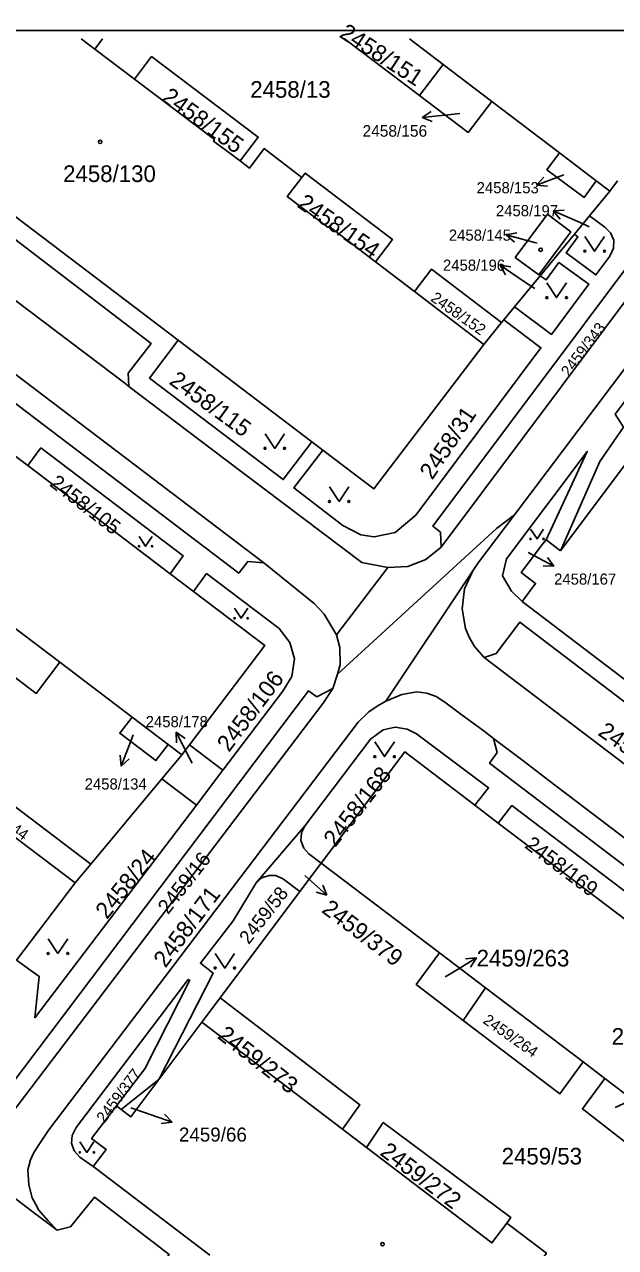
# Model space of a CAD drawing. Extents: x -606208 to -605570, y -1157873 to -1157573.
# Drawn here: x -605930.7 to -605870.3, y -1157700.9 to -1157575.9 of the extents above; entities that cross this region are included whole.
import ezdxf

# ---------------------------------------------------------------- set-up
doc = ezdxf.new("R2010")
doc.units = 0
doc.layers.add('Vrstva 1', color=7, linetype='Continuous')
doc.layers.add('Vrstva 62', color=7, linetype='Continuous')

msp = doc.modelspace()

# ---------------------------------------------------------------- linework, layer by layer
at = {"layer": 'Vrstva 1'}
msp.add_lwpolyline([(-606203.28, -1157873.46), (-605573.29, -1157873.46), (-605573.29, -1157576.47), (-606203.28, -1157576.47)], close=True, dxfattribs=at)
at = {"layer": 'Vrstva 62'}
for p, q in [((-605891.36, -1157577.34), (-605887.93, -1157579.95)), ((-605923.54, -1157578.38), (-605919.48, -1157581.46)), ((-605890.35, -1157583.14), (-605887.93, -1157579.95)), ((-605887.93, -1157579.95), (-605882.93, -1157583.75)), ((-605876.04, -1157588.98), (-605882.93, -1157583.75)), ((-605906.26, -1157630.89), (-605966.57, -1157585.11)), ((-605890.08, -1157585.38), (-605889.13, -1157584.78)), ((-605887.09, -1157585.07), (-605890.08, -1157585.38)), ((-605886.23, -1157584.98), (-605887.09, -1157585.07)), ((-605915.01, -1157608.14), (-605943.82, -1157586.26)), ((-605890.08, -1157585.38), (-605889.03, -1157585.78)), ((-605888.11, -1157629.29), (-605855.73, -1157585.95)), ((-605876.04, -1157588.98), (-605872.28, -1157591.84)), ((-605875.58, -1157591.22), (-605878.38, -1157592.29)), ((-605878.38, -1157592.29), (-605877.63, -1157591.47)), ((-605878.38, -1157592.29), (-605877.27, -1157592.4)), ((-605870.88, -1157592.9), (-605872.28, -1157591.84)), ((-605870.09, -1157591.86), (-605870.88, -1157592.9)), ((-605872.96, -1157595.43), (-605870.88, -1157592.9)), ((-605876.67, -1157594.9), (-605875.55, -1157594.85)), ((-605873.93, -1157596.12), (-605876.67, -1157594.9)), ((-605876.67, -1157594.9), (-605875.96, -1157595.76)), ((-605874.5, -1157597.3), (-605872.96, -1157595.43)), ((-605873, -1157596.54), (-605873.93, -1157596.12)), ((-605881.48, -1157597.38), (-605880.38, -1157597.16)), ((-605878.58, -1157598.16), (-605881.48, -1157597.38)), ((-605881.48, -1157597.38), (-605880.64, -1157598.13)), ((-605878, -1157601.55), (-605874.5, -1157597.3)), ((-605878.31, -1157598.23), (-605878.58, -1157598.16)), ((-605894.85, -1157600.12), (-605890.85, -1157603.17)), ((-605879.61, -1157602.16), (-605882.1, -1157600.48)), ((-605882.1, -1157600.48), (-605880.99, -1157600.63)), ((-605882.1, -1157600.48), (-605881.55, -1157601.46)), ((-605880.62, -1157604.74), (-605878, -1157601.55)), ((-605878.56, -1157602.87), (-605879.61, -1157602.16)), ((-605883.77, -1157608.56), (-605890.85, -1157603.17)), ((-605881.71, -1157606.06), (-605880.62, -1157604.74)), ((-605881.94, -1157606.34), (-605883.77, -1157608.56)), ((-605881.94, -1157606.34), (-605881.71, -1157606.06)), ((-605901.35, -1157618.51), (-605915.01, -1157608.14)), ((-605920.04, -1157612.86), (-605920.12, -1157611.51)), ((-605900.22, -1157619.37), (-605901.35, -1157618.51)), ((-605930.37, -1157620.95), (-605932.7, -1157619.19)), ((-605868.8, -1157620.15), (-605875.93, -1157629.65)), ((-605915.82, -1157632), (-605930.37, -1157620.95)), ((-605882.47, -1157627.39), (-605880.63, -1157625.97)), ((-605898.72, -1157642.27), (-605882.47, -1157627.39)), ((-605875.93, -1157629.65), (-605877.4, -1157628.53)), ((-605879.24, -1157629.83), (-605876.59, -1157631.24)), ((-605893.58, -1157631.36), (-605898.82, -1157638.24)), ((-605896.23, -1157630.86), (-605893.58, -1157631.36)), ((-605876.59, -1157631.24), (-605877.71, -1157631.21)), ((-605876.59, -1157631.24), (-605877.24, -1157630.33)), ((-605913.44, -1157633.81), (-605915.82, -1157632)), ((-605884.87, -1157631.71), (-605893.77, -1157645.04)), ((-605932.02, -1157637.34), (-605927.12, -1157641.05)), ((-605919.72, -1157646.65), (-605927.12, -1157641.05)), ((-605883.72, -1157640.58), (-605854.57, -1157662.74)), ((-605899.2, -1157643.74), (-605898.72, -1157642.27)), ((-605919.72, -1157646.65), (-605916.04, -1157649.44)), ((-605919.76, -1157648.86), (-605920.83, -1157651.66)), ((-605919.6, -1157648.47), (-605919.76, -1157648.86)), ((-605913.84, -1157650.85), (-605915.2, -1157648.18)), ((-605915.2, -1157648.18), (-605914.3, -1157648.84)), ((-605915.2, -1157648.18), (-605915.19, -1157649.3)), ((-605914.63, -1157650.5), (-605916.04, -1157649.44)), ((-605914.63, -1157650.5), (-605913.85, -1157649.48)), ((-605913.85, -1157649.48), (-605910.43, -1157652.08)), ((-605920.83, -1157651.66), (-605920.94, -1157650.55)), ((-605920.83, -1157651.66), (-605920.01, -1157650.91)), ((-605913.59, -1157651.35), (-605913.84, -1157650.85)), ((-605925.55, -1157663.59), (-605939.92, -1157652.7)), ((-605910.43, -1157652.08), (-605913.15, -1157655.66)), ((-605923.95, -1157661.67), (-605916.67, -1157652.97)), ((-605913.15, -1157655.66), (-605916.67, -1157652.97)), ((-605882.28, -1157657.48), (-605884.68, -1157655.65)), ((-605907.04, -1157663.6), (-605902.04, -1157657.75)), ((-605867.94, -1157668.37), (-605882.28, -1157657.48)), ((-605923.95, -1157661.67), (-605925.55, -1157663.59)), ((-605900.39, -1157661.58), (-605902.57, -1157664.49)), ((-605888.31, -1157670.75), (-605900.39, -1157661.58)), ((-605925.55, -1157663.59), (-605931.53, -1157671.5)), ((-605902.05, -1157662.85), (-605899.82, -1157664.86)), ((-605899.82, -1157664.86), (-605900.23, -1157663.82)), ((-605902.57, -1157664.49), (-605910.73, -1157675.36)), ((-605899.82, -1157664.86), (-605900.9, -1157664.56)), ((-605888.31, -1157670.75), (-605883.59, -1157674.33)), ((-605887.08, -1157672.82), (-605884.51, -1157671.27)), ((-605884.51, -1157671.27), (-605885.62, -1157671.36)), ((-605884.51, -1157671.27), (-605885.11, -1157672.22)), ((-605887.71, -1157673.19), (-605887.08, -1157672.82)), ((-605885.89, -1157677.65), (-605883.59, -1157674.33)), ((-605883.59, -1157674.33), (-605873.61, -1157681.9)), ((-605912.59, -1157677.83), (-605910.73, -1157675.36)), ((-605916.99, -1157683.7), (-605912.59, -1157677.83)), ((-605898.22, -1157688.76), (-605912.59, -1157677.83)), ((-605871.39, -1157683.59), (-605873.61, -1157681.9)), ((-605916.99, -1157683.7), (-605920.83, -1157686.75)), ((-605871.39, -1157683.59), (-605866.63, -1157687.2)), ((-605920.83, -1157686.75), (-605921.32, -1157686.38)), ((-605870.35, -1157686.55), (-605867.51, -1157685.27)), ((-605919.85, -1157686.58), (-605918.46, -1157687.06)), ((-605918.46, -1157687.06), (-605915.62, -1157688.04)), ((-605915.62, -1157688.04), (-605916.41, -1157687.24)), ((-605915.62, -1157688.04), (-605916.73, -1157688.18)), ((-605898.22, -1157688.76), (-605895.75, -1157690.64))]:
    msp.add_line(p, q, dxfattribs=at)
for points in [[(-605923.54, -1157578.38), (-605924.91, -1157577.34)], [(-605922.75, -1157577.34), (-605923.54, -1157578.38)], [(-605890.35, -1157583.14), (-605897.99, -1157577.34)], [(-605919.48, -1157581.46), (-605917.72, -1157579.15), (-605906.83, -1157587.38), (-605908.67, -1157589.82)], [(-605908.67, -1157589.82), (-605911.4, -1157587.78), (-605911.31, -1157587.64), (-605919.48, -1157581.46)], [(-605882.93, -1157583.75), (-605885.37, -1157586.92), (-605890.35, -1157583.14)], [(-605966.57, -1157585.11), (-605966.37, -1157586.46), (-605967.15, -1157587.67), (-605908.79, -1157631.94), (-605907.87, -1157630.75), (-605906.26, -1157630.89)], [(-605888.11, -1157629.29), (-605888.18, -1157627.77), (-605888.98, -1157627.14), (-605857.95, -1157585.72), (-605857.18, -1157586.29), (-605855.73, -1157585.95)], [(-605908.67, -1157589.82), (-605907.71, -1157590.54), (-605906.2, -1157588.55), (-605902.37, -1157591.5)], [(-605851.95, -1157588.15), (-605852.65, -1157588.89), (-605880.63, -1157625.97)], [(-605872.28, -1157591.84), (-605873.5, -1157593.54), (-605877.32, -1157590.71), (-605876.04, -1157588.98)], [(-605920.12, -1157611.51), (-605917.77, -1157608.48), (-605940.17, -1157591.39), (-605942.62, -1157594.56)], [(-605894.85, -1157600.12), (-605899.6, -1157596.5), (-605899.69, -1157596.63), (-605903.85, -1157593.46), (-605902.37, -1157591.5)], [(-605902.37, -1157591.5), (-605902.02, -1157591.05), (-605893.11, -1157597.83), (-605894.85, -1157600.12)], [(-605944.51, -1157594.38), (-605920.34, -1157612.64), (-605920.04, -1157612.86)], [(-605880.55, -1157599.67), (-605877.27, -1157595.25), (-605874.88, -1157597.05), (-605878.15, -1157601.45), (-605880.55, -1157599.67)], [(-605872.96, -1157595.43), (-605871.4, -1157596.58), (-605870.82, -1157597.15), (-605870.48, -1157597.92), (-605870.52, -1157598.74), (-605870.89, -1157599.55), (-605872.3, -1157601.47), (-605875.35, -1157599.22), (-605874.14, -1157597.57), (-605874.5, -1157597.3)], [(-605873.44, -1157597.54), (-605872.44, -1157599.04), (-605871.44, -1157597.54)], [(-605878, -1157601.55), (-605877.4, -1157601.97), (-605876.08, -1157600.18), (-605873.04, -1157602.4), (-605876.86, -1157607.54), (-605880.62, -1157604.74)], [(-605890.85, -1157603.17), (-605889.11, -1157600.87), (-605881.94, -1157606.34)], [(-605877.32, -1157602.29), (-605876.32, -1157603.79), (-605875.32, -1157602.29)], [(-605900.22, -1157619.37), (-605903.18, -1157623.23), (-605898.16, -1157627.06), (-605896.33, -1157628.04), (-605894.98, -1157628.24), (-605892.84, -1157627.8), (-605890.72, -1157626.01), (-605877.93, -1157608.91), (-605881.71, -1157606.06)], [(-605875.93, -1157629.65), (-605871.9, -1157620.54), (-605869.49, -1157617.02), (-605870.32, -1157615.7), (-605862.99, -1157605.9)], [(-605901.35, -1157618.51), (-605904.26, -1157622.39), (-605917.93, -1157612.01), (-605915.01, -1157608.14)], [(-605883.77, -1157608.56), (-605894.99, -1157623.34), (-605900.22, -1157619.37)], [(-605920.04, -1157612.86), (-605910.24, -1157620.28), (-605896.23, -1157630.86)], [(-605906.13, -1157617.69), (-605905.13, -1157619.19), (-605904.13, -1157617.69)], [(-605915.82, -1157632), (-605914.5, -1157630.17), (-605929.03, -1157619.14), (-605930.37, -1157620.95)], [(-605879.86, -1157634.83), (-605880.93, -1157633.77), (-605881.85, -1157632.23), (-605881.43, -1157630.49), (-605873.19, -1157619.51), (-605877.4, -1157628.53)], [(-605899.55, -1157623.11), (-605898.55, -1157624.61), (-605897.55, -1157623.11)], [(-605880.63, -1157625.97), (-605884.34, -1157630.88), (-605884.87, -1157631.71)], [(-605878.99, -1157627.44), (-605878.32, -1157628.45), (-605877.65, -1157627.44)], [(-605919.01, -1157628.19), (-605918.34, -1157629.2), (-605917.67, -1157628.19)], [(-605877.4, -1157628.53), (-605877.75, -1157628.99), (-605879.94, -1157631.88), (-605878.47, -1157633), (-605879.86, -1157634.83)], [(-605893.58, -1157631.36), (-605891.53, -1157631.26), (-605889.68, -1157630.54), (-605888.11, -1157629.29)], [(-605898.82, -1157638.24), (-605900.08, -1157636.15), (-605901.12, -1157635.03), (-605906.26, -1157630.89)], [(-605910.43, -1157652.08), (-605904.31, -1157643.99), (-605903.39, -1157642.5), (-605903.1, -1157640.71), (-605903.58, -1157639.02), (-605904.7, -1157637.6), (-605912.1, -1157631.99), (-605913.44, -1157633.81)], [(-605884.87, -1157631.71), (-605885.74, -1157633.55), (-605885.98, -1157635.59), (-605885.64, -1157637.61), (-605885.26, -1157638.48), (-605884.72, -1157639.43), (-605883.72, -1157640.58)], [(-605913.85, -1157649.48), (-605906.14, -1157639.35), (-605913.44, -1157633.81)], [(-605879.86, -1157634.83), (-605869.57, -1157642.64), (-605866.75, -1157644.79), (-605858.45, -1157651.08), (-605848.95, -1157658.29)], [(-605909.24, -1157635.54), (-605908.57, -1157636.55), (-605907.9, -1157635.54)], [(-605883.72, -1157640.58), (-605882.51, -1157640.16), (-605880.08, -1157636.95), (-605852.25, -1157658.15), (-605854.64, -1157661.35), (-605854.57, -1157662.74)], [(-605898.82, -1157638.24), (-605898.49, -1157639.53), (-605898.45, -1157641.32), (-605898.72, -1157642.27)], [(-605927.12, -1157641.05), (-605929.53, -1157644.24), (-605934.44, -1157640.52)], [(-605899.2, -1157643.74), (-605900.85, -1157644.58), (-605901.7, -1157643.98), (-605933.59, -1157686.19), (-605932.13, -1157687.27)], [(-605932.13, -1157687.27), (-605900.17, -1157645.24), (-605899.2, -1157643.74)], [(-605893.77, -1157645.04), (-605894.65, -1157645.53), (-605895.51, -1157646.11), (-605896.61, -1157647.19), (-605915.55, -1157672.14), (-605928.22, -1157688.83), (-605929.13, -1157690.18), (-605929.75, -1157691.16), (-605930.12, -1157691.91), (-605930.37, -1157692.94), (-605930.31, -1157693.93), (-605930.28, -1157694.46), (-605929.92, -1157695.78), (-605929.39, -1157696.77), (-605929.27, -1157697), (-605928.3, -1157698.15), (-605927.39, -1157699.1)], [(-605882.77, -1157648.83), (-605883.72, -1157648.11), (-605886.11, -1157646.34), (-605887.76, -1157645.12), (-605888.62, -1157644.55), (-605889.6, -1157644.2), (-605890.61, -1157644.09), (-605892.14, -1157644.33), (-605893.77, -1157645.04)], [(-605916.04, -1157649.44), (-605917.29, -1157651.1), (-605920.98, -1157648.3), (-605919.72, -1157646.65)], [(-605902.04, -1157657.75), (-605895.34, -1157648.92), (-605894.04, -1157647.97), (-605892.83, -1157647.7), (-605891.61, -1157647.88), (-605890.64, -1157648.37), (-605883.28, -1157653.88), (-605884.68, -1157655.65)], [(-605822.96, -1157694.27), (-605824.7, -1157694.08), (-605825.52, -1157695.16), (-605883.17, -1157651.37), (-605882.4, -1157650.28), (-605882.77, -1157648.83)], [(-605822.96, -1157694.27), (-605823.13, -1157694.14), (-605837.5, -1157683.23), (-605847.55, -1157675.59), (-605851.06, -1157672.93), (-605858.82, -1157667.03), (-605867.01, -1157660.81), (-605869.19, -1157659.16), (-605877.11, -1157653.13), (-605879.78, -1157651.1), (-605882.77, -1157648.83)], [(-605884.68, -1157655.65), (-605891.85, -1157650.21), (-605900.39, -1157661.58)], [(-605894.91, -1157649.2), (-605893.91, -1157650.7), (-605892.91, -1157649.2)], [(-605939.92, -1157652.7), (-605938.41, -1157650.71), (-605923.95, -1157661.67)], [(-605916.67, -1157652.97), (-605914.72, -1157650.64), (-605914.63, -1157650.5)], [(-605931.53, -1157671.5), (-605929.23, -1157673.15), (-605929.66, -1157677.39), (-605913.15, -1157655.66)], [(-605882.28, -1157657.48), (-605880.89, -1157655.7), (-605866.53, -1157666.6), (-605867.94, -1157668.37)], [(-605902.04, -1157657.75), (-605902.41, -1157658.5), (-605902.47, -1157659.27), (-605902.17, -1157660.05), (-605901.65, -1157660.62), (-605900.39, -1157661.58)], [(-605907.04, -1157663.6), (-605909.39, -1157667.47), (-605912.73, -1157671.81), (-605911.44, -1157672.81), (-605916.99, -1157683.7)], [(-605902.57, -1157664.49), (-605904.24, -1157663.22), (-605905.01, -1157662.86), (-605905.72, -1157662.83), (-605906.44, -1157663.08), (-605907.04, -1157663.6)], [(-605928.3, -1157669.31), (-605927.3, -1157670.81), (-605926.3, -1157669.31)], [(-605911.24, -1157670.8), (-605910.24, -1157672.3), (-605909.24, -1157670.8)], [(-605885.89, -1157677.65), (-605890.67, -1157673.97), (-605888.31, -1157670.75)], [(-605923.7, -1157692.57), (-605925.07, -1157691.63), (-605925.64, -1157690.97), (-605925.91, -1157690.19), (-605925.85, -1157689.43), (-605925.44, -1157688.59), (-605913.99, -1157673.46), (-605913.82, -1157673.53), (-605918.43, -1157682.6), (-605921.32, -1157686.38)], [(-605910.73, -1157675.36), (-605896.43, -1157686.29), (-605898.22, -1157688.76)], [(-605873.61, -1157681.9), (-605875.99, -1157685.15), (-605885.89, -1157677.65)], [(-605920.83, -1157686.75), (-605919.84, -1157687.5), (-605916.99, -1157683.7)], [(-605869.06, -1157690.28), (-605873.69, -1157686.7), (-605871.39, -1157683.59)], [(-605921.32, -1157686.38), (-605923.86, -1157689.72), (-605922.38, -1157690.84), (-605923.7, -1157692.57)], [(-605927.39, -1157699.1), (-605929.95, -1157697.15), (-605942.14, -1157687.85)], [(-605895.75, -1157690.64), (-605894.04, -1157688.1), (-605880.99, -1157697.8), (-605881.41, -1157698.37)], [(-605925.06, -1157690.07), (-605924.34, -1157691.15), (-605923.62, -1157690.07)], [(-605881.41, -1157698.37), (-605882.94, -1157700.39), (-605895.75, -1157690.64)], [(-605923.7, -1157692.57), (-605923.46, -1157692.75), (-605911.76, -1157701.63)], [(-605918.08, -1157706.18), (-605918.33, -1157704.72), (-605915.93, -1157701.57), (-605923.57, -1157695.72), (-605926.03, -1157698.76), (-605927.39, -1157699.1)], [(-605881.41, -1157698.37), (-605877.36, -1157701.44), (-605878.85, -1157703.49), (-605876.65, -1157705.17)]]:
    msp.add_lwpolyline(points, dxfattribs=at)
for centre, radius in [((-605922.98, -1157587.87), 0.175), ((-605877.95, -1157598.89), 0.175), ((-605873.44, -1157599.04), 0.1), ((-605871.44, -1157599.04), 0.1), ((-605877.32, -1157603.79), 0.1), ((-605875.32, -1157603.79), 0.1), ((-605906.13, -1157619.19), 0.1), ((-605904.13, -1157619.19), 0.1), ((-605899.55, -1157624.61), 0.1), ((-605897.55, -1157624.61), 0.1), ((-605878.99, -1157628.45), 0.067), ((-605877.65, -1157628.45), 0.067), ((-605919.01, -1157629.2), 0.067), ((-605917.67, -1157629.2), 0.067), ((-605909.24, -1157636.55), 0.067), ((-605907.9, -1157636.55), 0.067), ((-605894.91, -1157650.7), 0.1), ((-605892.91, -1157650.7), 0.1), ((-605928.3, -1157670.81), 0.1), ((-605926.3, -1157670.81), 0.1), ((-605911.24, -1157672.3), 0.1), ((-605909.24, -1157672.3), 0.1), ((-605925.06, -1157691.15), 0.072), ((-605923.62, -1157691.15), 0.072), ((-605894.12, -1157700.53), 0.175)]:
    msp.add_circle(centre, radius, dxfattribs=at)

# ---------------------------------------------------------------- texts
for s, height, rotation, p in [('2458/151', 1.7, 327, (-605898.64, -1157577.09)), ('2458/155', 1.7, 324, (-605916.79, -1157583.57)), ('2458/154', 1.7, 325, (-605902.94, -1157594.45)), ('2458/152', 1.139, 325, (-605889.28, -1157604.05)), ('2459/343', 1.139, 53, (-605875.06, -1157611.95)), ('2458/115', 1.7, 324, (-605916.03, -1157612.54)), ('2458/31', 1.7, 56, (-605889.04, -1157622.49)), ('2458/105', 1.5, 322, (-605928.24, -1157622.95)), ('2458/106', 1.7, 53, (-605909.82, -1157650.32)), ('2458/166', 1.7, 325, (-605872.2, -1157648.43)), ('2458/168', 1.7, 52, (-605898.96, -1157660.04)), ('2458/144', 1.139, 325, (-605936.03, -1157655.67)), ('2458/169', 1.535, 323, (-605879.68, -1157659.94)), ('2458/24', 1.7, 51, (-605922.29, -1157667.4)), ('2459/16', 1.5, 52, (-605916.04, -1157666.9)), ('2458/171', 1.7, 53, (-605916.31, -1157672.36)), ('2459/58', 1.386, 52, (-605907.79, -1157669.96)), ('2459/379', 1.7, 323, (-605900.44, -1157666.53)), ('2459/264', 1.139, 325, (-605883.94, -1157677.86)), ('2459/273', 1.7, 322, (-605911.09, -1157679.4)), ('2459/377', 1.139, 53, (-605922.55, -1157688.22)), ('2459/272', 1.7, 323, (-605894.48, -1157691.33))]:
    msp.add_text(s, height=height, rotation=rotation, dxfattribs=at).set_placement(p)
for s, height, p in [('2458/13', 1.7, (-605907.64, -1157583.36)), ('2458/156', 1.184, (-605896.16, -1157587.34)), ('2458/130', 1.7, (-605926.77, -1157591.97)), ('2458/153', 1.14, (-605884.5, -1157593.12)), ('2458/197', 1.139, (-605882.53, -1157595.47)), ('2458/145', 1.139, (-605887.34, -1157597.97)), ('2458/196', 1.139, (-605887.94, -1157601.04)), ('2458/167', 1.139, (-605876.58, -1157633.12)), ('2458/178', 1.139, (-605918.33, -1157647.69)), ('2458/134', 1.139, (-605924.57, -1157654.06)), ('2459/263', 1.7, (-605884.5, -1157672.14)), ('2459/234', 1.7, (-605870.69, -1157680.14)), ('2459/66', 1.436, (-605914.93, -1157690.04)), ('2459/53', 1.7, (-605881.94, -1157692.38))]:
    msp.add_text(s, height=height, dxfattribs=at).set_placement(p)

doc.saveas('drawing.dxf')
